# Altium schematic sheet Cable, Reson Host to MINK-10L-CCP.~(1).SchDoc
size B; Organization: Monterey Bay Aquarium Research Institute; Address1: 7700 Sandholdt Rd; Address2: Moss Landing, CA 95039-9644; CompanyName: MBARI
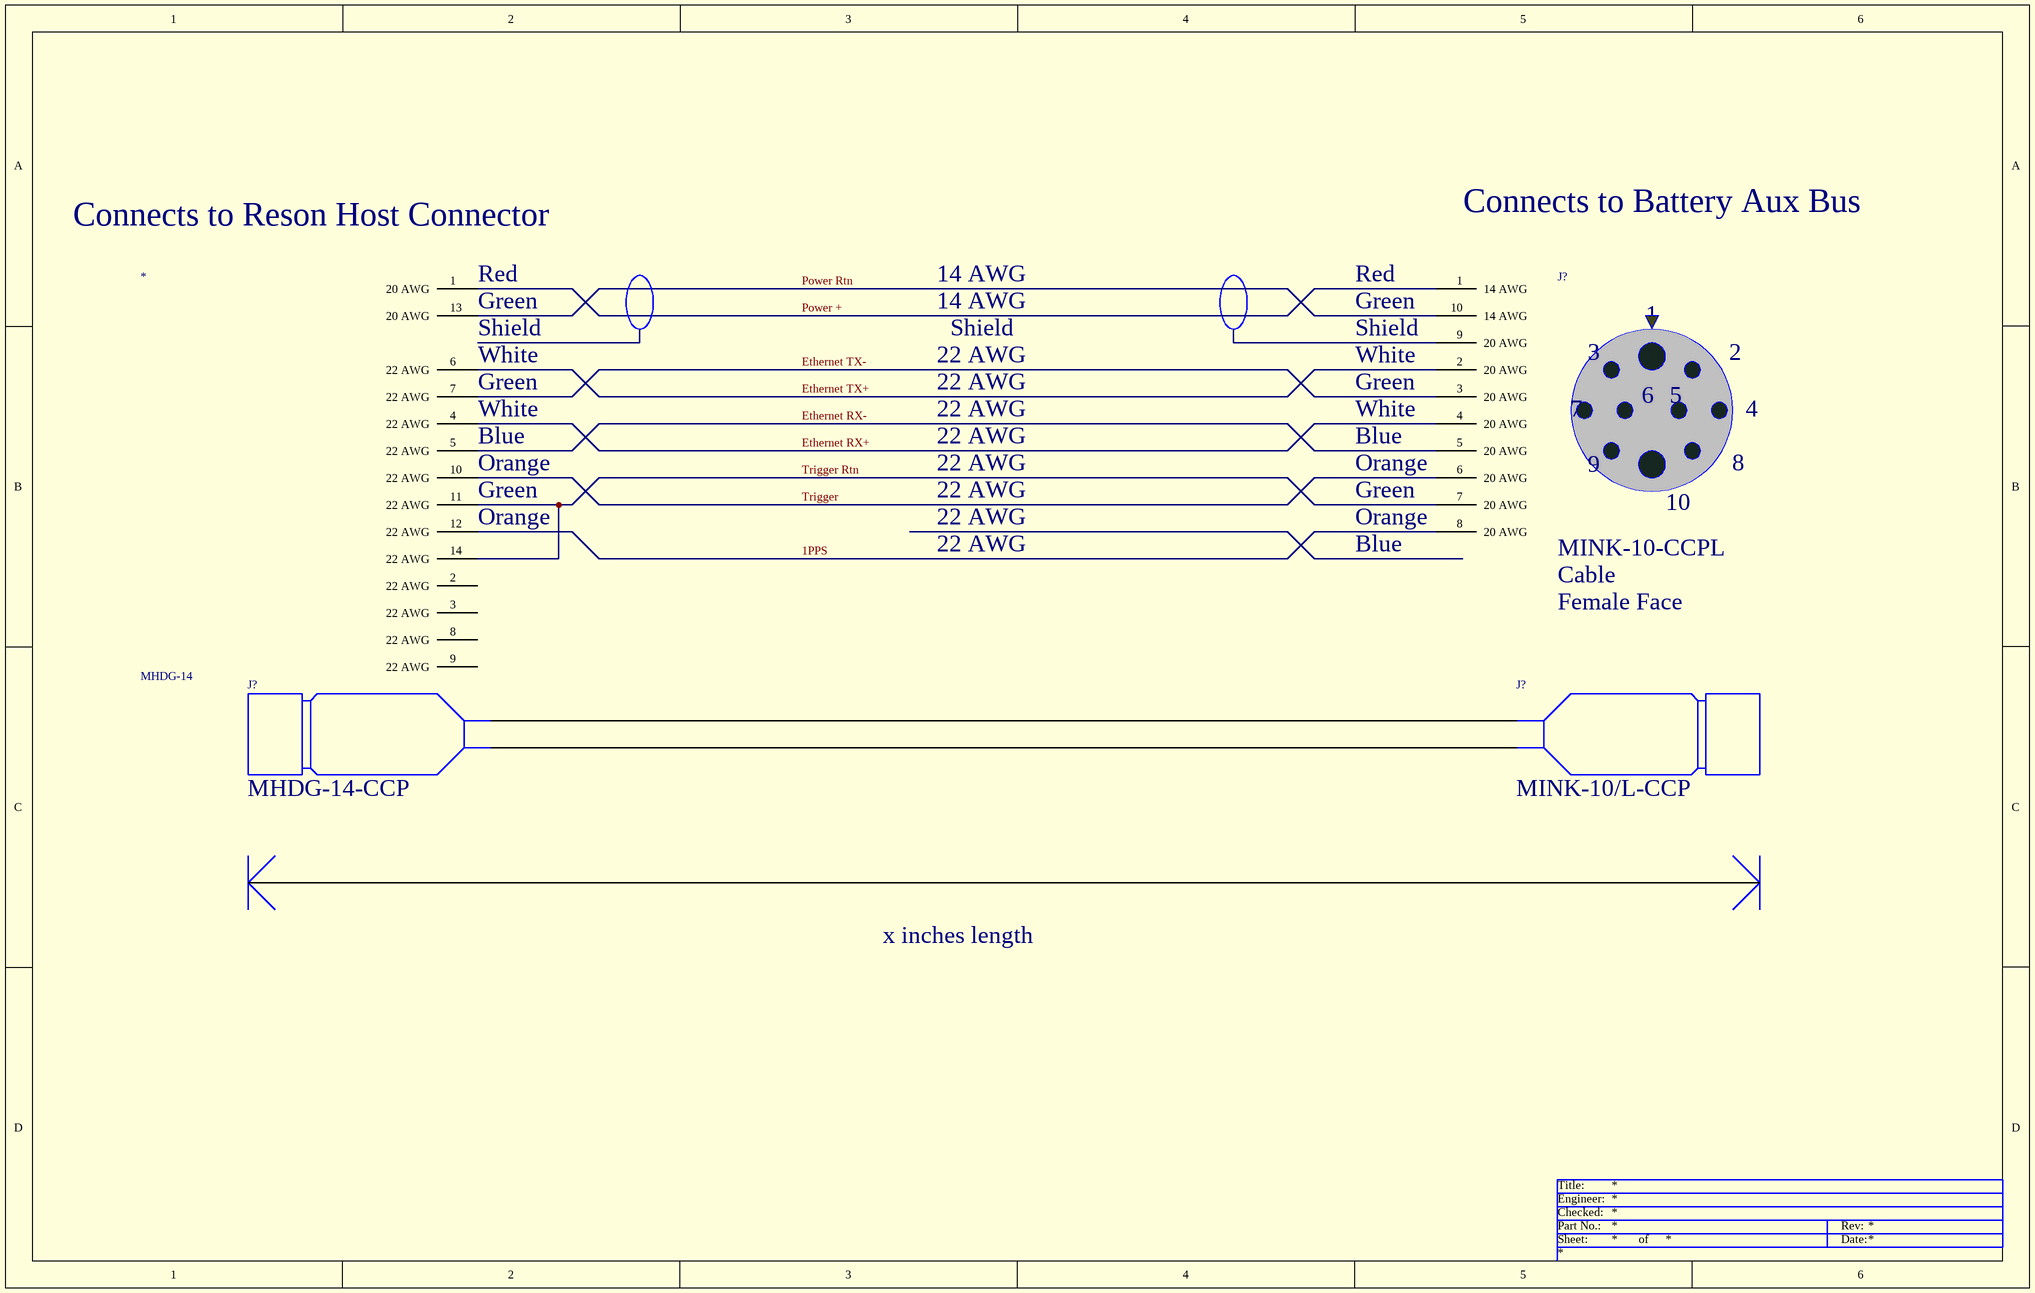
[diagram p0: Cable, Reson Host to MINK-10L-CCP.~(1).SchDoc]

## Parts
(Parts that share a designator on the sheet are numbered #1, #2 ... from top to bottom, then left to right.)
*  MHDG-14
J?#1  MINK-10-CCPL  DescSheet: Cable  View: Female Face
J?#2  MHDG-14-CCP
J?#3  MINK-10/L-CCP

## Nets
1PPS: *.12(22_AWG) J?#1.8(20_AWG)
Ethernet RX+: *.4(22_AWG) J?#1.4(20_AWG)
Ethernet RX-: *.5(22_AWG) J?#1.5(20_AWG)
Ethernet TX+: *.6(22_AWG) J?#1.2(20_AWG)
Ethernet TX-: *.7(22_AWG) J?#1.3(20_AWG)
Power +: *.1(20_AWG) J?#1.1(14_AWG)
Power Rtn: *.13(20_AWG) J?#1.10(14_AWG)
Trigger: *.10(22_AWG) J?#1.6(20_AWG)
Trigger Rtn: *.11(22_AWG) *.14(22_AWG) J?#1.7(20_AWG)

Not connected (* = marked no-connect by the designer): * 2(22_AWG) 3(22_AWG) 8(22_AWG) 9(22_AWG); J?#1 9(20_AWG)

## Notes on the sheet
- Connects to Reson Host Connector
- Connects to Battery Aux Bus
- (near *) Red
- 14 AWG
- Red
- (near *) Green
- (near *) Shield
- (near *) White
- 22 AWG
- Shield
- Green
- (near J?#1) Shield
- White
- (near *) Blue
- (near *) Orange
- Blue
- (near J?#1) Orange
- x inches length

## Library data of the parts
J?#1 = SEACON-MINK-10-CCP-SOC: Seacon MINK-10/L-CCP Connector
J?#2 J?#3 = CONN-MIN-CCP-LARGE: Seacon MIN Connector CCP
